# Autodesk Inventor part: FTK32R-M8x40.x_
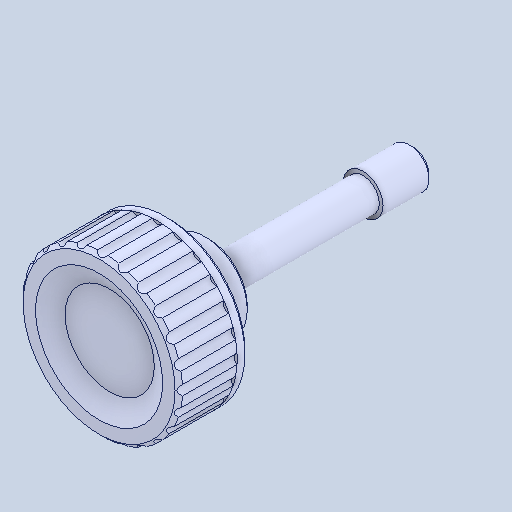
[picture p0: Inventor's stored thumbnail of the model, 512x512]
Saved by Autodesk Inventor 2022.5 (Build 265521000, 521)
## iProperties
Created: 2024-06
Part Number: FTK32R-M8x40.x_
Material: 一般
Document SubType Name: Modeling
Designer: ImaoCorp
Density: 1 g/cm^3
Appearance: 既定
Author: ImaoCorp
Sending System: SOLIDWORKS 2022-2022290
MC: AMD64
MC_MODEL: Intel64 Family 6 Model 60 Stepping 3, GenuineIntel
OS: Windows_NT
FRU: Parasolid Version 33.1, build 260,  4-25-2022
FORMAT: text
GUISE: transmit
KEY: FILEFTK32R-M8x40.x_t
DATE: Fri Jun 28 15:20:54 2024
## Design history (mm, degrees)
feature "Captive grooved knobs BT-HP.32-p-M8x40"
node "ソリッド1"
